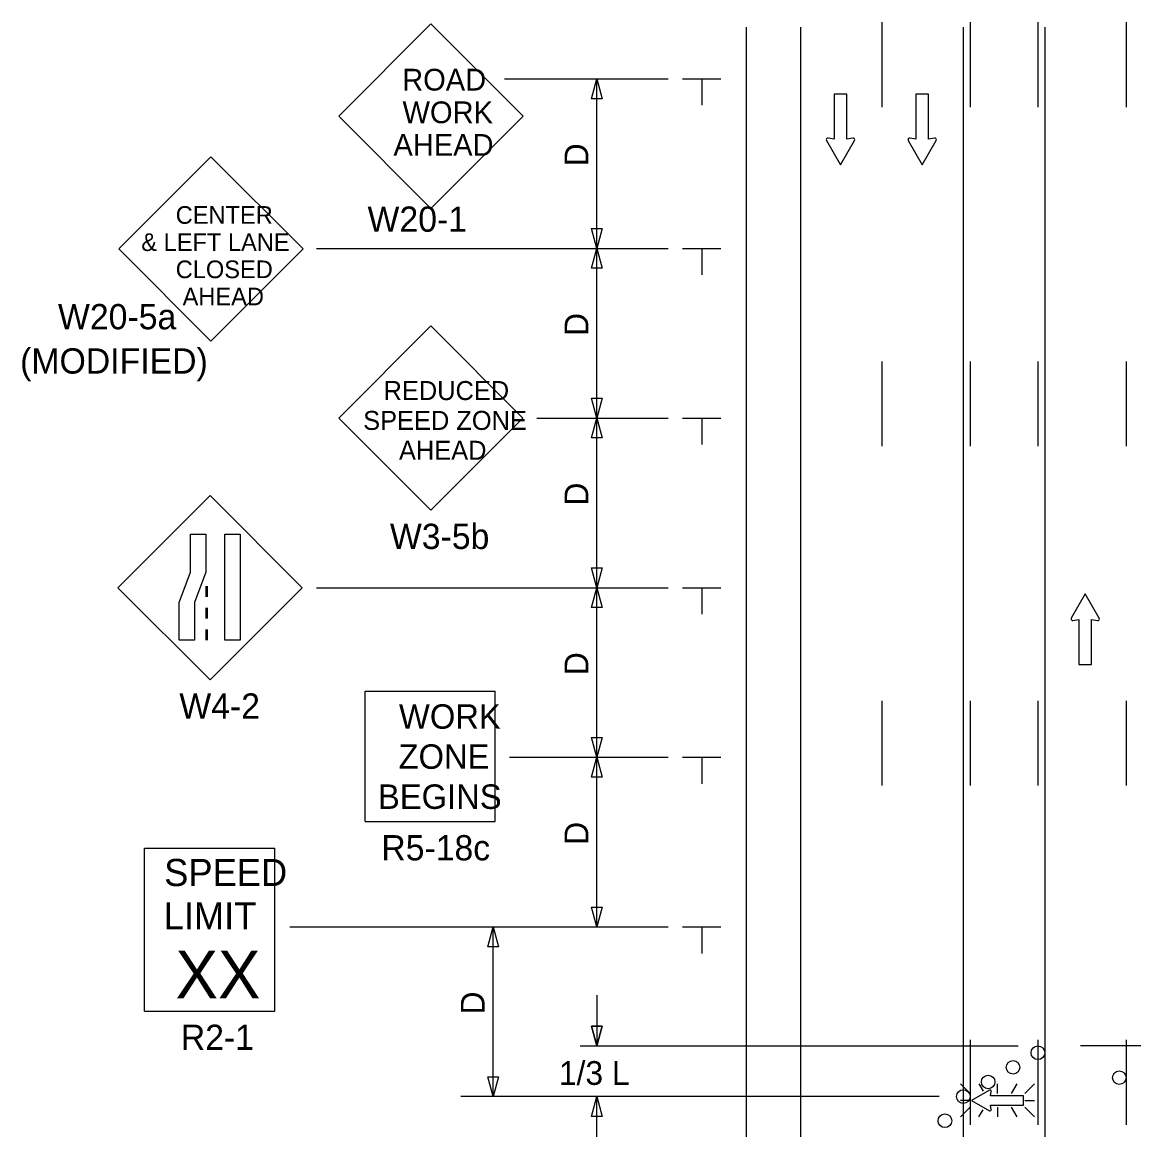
# Model space of a CAD drawing. Extents: x 16731 to 18475, y 5706 to 6928.
# Drawn here: x 16734 to 17061.7, y 6601.4 to 6927.9 of the extents above; entities that cross this region are included whole.
import ezdxf

# ---------------------------------------------------------------- set-up
doc = ezdxf.new("R2010")
doc.units = 0
for name, color, linetype in [('ALI_LEGAL_EX', 7, 'Continuous'), ('MT_SCRATCH_LEVEL_E', 7, 'Continuous'), ('PAVT_EDGE_EX', 7, 'Continuous'), ('TRAFFIC_SIGNS_PR', 7, 'Continuous'), ('TYPICAL_TEXT_DIMEN_PR', 7, 'Continuous')]:
    doc.layers.add(name, color=color, linetype=linetype)

msp = doc.modelspace()

# ---------------------------------------------------------------- linework, layer by layer
at = {"layer": 'ALI_LEGAL_EX'}
for points in [[(16987.43, 6927.88), (16987.43, 6902.88)], [(17013.43, 6927.88), (17013.43, 6902.88)], [(17033.43, 6927.88), (17033.43, 6902.88)], [(17059.43, 6927.88), (17059.43, 6902.88)], [(16987.43, 6827.88), (16987.43, 6802.88)], [(17013.43, 6827.88), (17013.43, 6802.88)], [(17033.43, 6827.88), (17033.43, 6802.88)], [(17059.43, 6827.88), (17059.43, 6802.88)], [(16987.43, 6727.88), (16987.43, 6702.88)], [(17013.43, 6727.88), (17013.43, 6702.88)], [(17033.43, 6727.88), (17033.43, 6702.88)], [(17059.43, 6727.88), (17059.43, 6702.88)], [(17013.43, 6627.88), (17013.43, 6602.88)], [(17033.43, 6627.88), (17033.43, 6602.88)], [(17059.43, 6627.88), (17059.43, 6602.88)]]:
    msp.add_lwpolyline(points, dxfattribs=at)
at = {"layer": 'MT_SCRATCH_LEVEL_E'}
for p, q in [((16977.1, 6906.67), (16973.36, 6906.67)), ((16973.36, 6906.67), (16973.36, 6893.41)), ((16977.1, 6906.67), (16973.36, 6906.67)), ((16973.36, 6906.67), (16973.36, 6893.41)), ((16977.1, 6893.41), (16977.1, 6906.67)), ((16977.1, 6893.41), (16977.1, 6906.67)), ((17001.17, 6906.67), (16997.43, 6906.67)), ((16997.43, 6906.67), (16997.43, 6893.41)), ((17001.17, 6906.67), (16997.43, 6906.67)), ((16997.43, 6906.67), (16997.43, 6893.41)), ((17001.17, 6893.41), (17001.17, 6906.67)), ((17001.17, 6893.41), (17001.17, 6906.67)), ((16971.1, 6893.05), (16975.25, 6885.81)), ((16971.1, 6893.05), (16975.25, 6885.81)), ((16973.36, 6893.41), (16971.58, 6893.73)), ((16973.36, 6893.41), (16971.58, 6893.73)), ((16975.25, 6885.81), (16979.36, 6893.05)), ((16975.25, 6885.81), (16979.36, 6893.05)), ((16978.88, 6893.73), (16977.1, 6893.41)), ((16978.88, 6893.73), (16977.1, 6893.41)), ((16995.18, 6893.05), (16999.32, 6885.81)), ((16995.18, 6893.05), (16999.32, 6885.81)), ((16997.43, 6893.41), (16995.65, 6893.73)), ((16997.43, 6893.41), (16995.65, 6893.73)), ((16999.32, 6885.81), (17003.43, 6893.05)), ((16999.32, 6885.81), (17003.43, 6893.05)), ((17002.95, 6893.73), (17001.17, 6893.41)), ((17002.95, 6893.73), (17001.17, 6893.41)), ((17047.37, 6759.44), (17043.26, 6752.2)), ((17047.37, 6759.44), (17043.26, 6752.2)), ((17051.52, 6752.2), (17047.37, 6759.44)), ((17051.52, 6752.2), (17047.37, 6759.44)), ((17043.74, 6751.51), (17045.52, 6751.83)), ((17043.74, 6751.51), (17045.52, 6751.83)), ((17045.52, 6751.83), (17045.52, 6738.57)), ((17045.52, 6751.83), (17045.52, 6738.57)), ((17049.26, 6738.57), (17049.26, 6751.83)), ((17049.26, 6751.83), (17051.04, 6751.51)), ((17049.26, 6738.57), (17049.26, 6751.83)), ((17049.26, 6751.83), (17051.04, 6751.51)), ((17045.52, 6738.57), (17049.26, 6738.57)), ((17045.52, 6738.57), (17049.26, 6738.57))]:
    msp.add_line(p, q, dxfattribs=at)
for centre, start, end in [((16971.51, 6893.27), 80.0362, 209.7731), ((16971.51, 6893.27), 80.0362, 209.7731), ((16978.96, 6893.27), 330.4248, 99.9638), ((16978.96, 6893.27), 330.4248, 99.9638), ((16995.59, 6893.27), 80.0362, 209.7731), ((16995.59, 6893.27), 80.0362, 209.7731), ((17003.03, 6893.27), 330.4248, 99.9638), ((17003.03, 6893.27), 330.4248, 99.9638), ((17043.67, 6751.97), 150.4248, 279.9638), ((17043.67, 6751.97), 150.4248, 279.9638), ((17051.11, 6751.97), 260.0362, 29.7731), ((17051.11, 6751.97), 260.0362, 29.7731)]:
    msp.add_arc(centre, 0.463, start, end, dxfattribs=at)
at = {"layer": 'PAVT_EDGE_EX'}
for p, q in [((16947.43, 6926.45), (16947.43, 6059.71)), ((16963.43, 6926.45), (16963.43, 6059.71)), ((17011.43, 6926.45), (17011.43, 6059.71)), ((17035.43, 6926.45), (17035.43, 6059.71))]:
    msp.add_line(p, q, dxfattribs=at)
at = {"layer": 'TRAFFIC_SIGNS_PR'}
for p, q in [((16854.47, 6927.38), (16827.28, 6900.19)), ((16881.66, 6900.19), (16854.47, 6927.38)), ((16827.28, 6900.19), (16854.47, 6873.01)), ((16854.47, 6873.01), (16881.66, 6900.19)), ((16789.62, 6888.24), (16762.43, 6861.05)), ((16816.81, 6861.05), (16789.62, 6888.24)), ((16762.43, 6861.05), (16789.62, 6833.86)), ((16789.62, 6833.86), (16816.81, 6861.05)), ((16854.45, 6838.36), (16827.3, 6811.2)), ((16881.6, 6811.2), (16854.45, 6838.36)), ((16827.3, 6811.2), (16854.45, 6784.05)), ((16854.45, 6784.05), (16881.6, 6811.2)), ((16789.36, 6788.36), (16762.2, 6761.2)), ((16816.51, 6761.2), (16789.36, 6788.36)), ((16762.2, 6761.2), (16789.36, 6734.05)), ((16788.11, 6761.69), (16788.11, 6758.49)), ((16788.51, 6761.69), (16788.51, 6758.49)), ((16789.36, 6734.05), (16816.51, 6761.2)), ((16788.11, 6755.29), (16788.11, 6752.09)), ((16788.51, 6755.29), (16788.51, 6752.09)), ((16788.11, 6748.89), (16788.11, 6745.69)), ((16788.51, 6748.89), (16788.51, 6745.69)), ((16835.05, 6692.26), (16835.05, 6730.66)), ((16835.05, 6730.66), (16873.45, 6730.66)), ((16873.45, 6692.26), (16873.45, 6730.66)), ((16835.05, 6692.26), (16873.45, 6692.26)), ((16770.07, 6684.4), (16808.47, 6684.4)), ((16770.07, 6636.4), (16770.07, 6684.4)), ((16808.47, 6636.4), (16808.47, 6684.4)), ((16770.07, 6636.4), (16808.47, 6636.4)), ((17010.62, 6614.93), (17013.44, 6612.11)), ((17017.34, 6612.75), (17016.08, 6614.93)), ((17021.52, 6612.11), (17021.52, 6614.93)), ((17025.65, 6612.11), (17027.28, 6614.93)), ((17029.6, 6612.11), (17032.43, 6614.93)), ((17013.44, 6610.08), (17010.62, 6610.08)), ((17029.6, 6610.08), (17032.43, 6610.08)), ((17010.62, 6605.23), (17013.44, 6608.05)), ((17016.05, 6605.23), (17017.26, 6607.32)), ((17021.52, 6608.05), (17021.52, 6605.23)), ((17027.31, 6605.23), (17025.68, 6608.05)), ((17029.6, 6608.05), (17032.43, 6605.23))]:
    msp.add_line(p, q, dxfattribs=at)
for points in [[(16788.11, 6776.94), (16788.11, 6765.76), (16784.77, 6756.88), (16784.77, 6745.69), (16780.27, 6745.69), (16780.27, 6756.88), (16783.62, 6765.76), (16783.62, 6776.94)], [(16798.25, 6776.94), (16798.25, 6745.69), (16793.75, 6745.69), (16793.75, 6776.94)]]:
    msp.add_lwpolyline(points, close=True, dxfattribs=at)
for points in [[(17019.19, 6613.1), (17013.88, 6610.08), (17019.19, 6607.04)], [(17019.69, 6607.4), (17019.46, 6608.69), (17029.19, 6608.69), (17029.19, 6611.44), (17019.46, 6611.44), (17019.69, 6612.74)]]:
    msp.add_lwpolyline(points, dxfattribs=at)
for centre in [(17033.42, 6624.12), (17026.09, 6619.82), (17018.76, 6615.51), (17057.41, 6616.77), (17011.43, 6611.2), (17006.01, 6604.07)]:
    msp.add_circle(centre, 2, dxfattribs=at)
for centre, start, end in [((17019.36, 6612.8), 350.7308, 118.8916), ((17019.36, 6607.34), 241.4833, 9.9593)]:
    msp.add_arc(centre, 0.341, start, end, dxfattribs=at)
at = {"layer": 'TYPICAL_TEXT_DIMEN_PR'}
for p, q in [((16876.2, 6911.2), (16924.43, 6911.2)), ((16901.86, 6905.34), (16903.43, 6911.2)), ((16903.43, 6861.2), (16903.43, 6911.2)), ((16903.43, 6911.2), (16905, 6905.34)), ((16928.68, 6911.2), (16939.93, 6911.2)), ((16934.31, 6911.2), (16934.31, 6903.42)), ((16903.43, 6905.34), (16901.86, 6905.34)), ((16905, 6905.34), (16903.43, 6905.34)), ((16903.43, 6861.2), (16901.86, 6867.07)), ((16901.86, 6867.07), (16903.43, 6867.07)), ((16903.43, 6867.07), (16905, 6867.07)), ((16905, 6867.07), (16903.43, 6861.2)), ((16820.78, 6861.2), (16924.43, 6861.2)), ((16898.43, 6861.2), (16924.43, 6861.2)), ((16901.86, 6855.34), (16903.43, 6861.2)), ((16903.43, 6811.2), (16903.43, 6861.2)), ((16903.43, 6861.2), (16905, 6855.34)), ((16928.68, 6861.2), (16939.93, 6861.2)), ((16934.31, 6861.2), (16934.31, 6853.42)), ((16903.43, 6855.34), (16901.86, 6855.34)), ((16905, 6855.34), (16903.43, 6855.34)), ((16903.43, 6811.2), (16901.86, 6817.07)), ((16901.86, 6817.07), (16903.43, 6817.07)), ((16903.43, 6817.07), (16905, 6817.07)), ((16905, 6817.07), (16903.43, 6811.2)), ((16885.75, 6811.2), (16924.43, 6811.2)), ((16898.43, 6811.2), (16924.43, 6811.2)), ((16901.86, 6805.34), (16903.43, 6811.2)), ((16903.43, 6811.2), (16905, 6805.34)), ((16903.43, 6761.2), (16903.43, 6811.2)), ((16928.68, 6811.2), (16939.93, 6811.2)), ((16934.31, 6811.2), (16934.31, 6803.42)), ((16903.43, 6805.34), (16901.86, 6805.34)), ((16905, 6805.34), (16903.43, 6805.34)), ((16903.43, 6761.2), (16901.86, 6767.07)), ((16901.86, 6767.07), (16903.43, 6767.07)), ((16903.43, 6767.07), (16905, 6767.07)), ((16905, 6767.07), (16903.43, 6761.2)), ((16820.78, 6761.2), (16924.43, 6761.2)), ((16901.86, 6755.34), (16903.43, 6761.2)), ((16903.43, 6761.2), (16905, 6755.34)), ((16903.43, 6711.2), (16903.43, 6761.2)), ((16928.68, 6761.2), (16939.93, 6761.2)), ((16934.31, 6761.2), (16934.31, 6753.42)), ((16903.43, 6755.34), (16901.86, 6755.34)), ((16905, 6755.34), (16903.43, 6755.34)), ((16903.43, 6711.2), (16901.86, 6717.07)), ((16901.86, 6717.07), (16903.43, 6717.07)), ((16903.43, 6717.07), (16905, 6717.07)), ((16905, 6717.07), (16903.43, 6711.2)), ((16877.68, 6711.2), (16924.43, 6711.2)), ((16901.86, 6705.34), (16903.43, 6711.2)), ((16903.43, 6711.2), (16905, 6705.34)), ((16903.43, 6661.2), (16903.43, 6711.2)), ((16928.68, 6711.2), (16939.93, 6711.2)), ((16934.31, 6711.2), (16934.31, 6703.42)), ((16903.43, 6705.34), (16901.86, 6705.34)), ((16905, 6705.34), (16903.43, 6705.34)), ((16903.43, 6661.2), (16901.86, 6667.07)), ((16901.86, 6667.07), (16903.43, 6667.07)), ((16903.43, 6667.07), (16905, 6667.07)), ((16905, 6667.07), (16903.43, 6661.2)), ((16812.89, 6661.2), (16924.43, 6661.2)), ((16871.29, 6655.34), (16872.86, 6661.2)), ((16872.86, 6611.2), (16872.86, 6661.2)), ((16872.86, 6661.2), (16874.43, 6655.34)), ((16928.68, 6661.2), (16939.93, 6661.2)), ((16934.31, 6661.2), (16934.31, 6653.42)), ((16872.86, 6655.34), (16871.29, 6655.34)), ((16874.43, 6655.34), (16872.86, 6655.34)), ((16903.43, 6641.05), (16903.43, 6626.12)), ((16903.43, 6626.12), (16901.86, 6631.99)), ((16901.86, 6631.99), (16903.43, 6631.99)), ((16903.43, 6631.99), (16901.86, 6631.99)), ((16901.86, 6631.99), (16903.43, 6626.12)), ((16903.43, 6631.99), (16905, 6631.99)), ((16905, 6631.99), (16903.43, 6626.12)), ((16903.43, 6626.12), (16905, 6631.99)), ((16905, 6631.99), (16903.43, 6631.99)), ((16898.43, 6626.12), (17027.57, 6626.12)), ((16898.43, 6626.12), (17000.85, 6626.12)), ((17148.43, 6626.12), (17046.02, 6626.12)), ((16872.86, 6611.2), (16871.29, 6617.07)), ((16871.29, 6617.07), (16872.86, 6617.07)), ((16872.86, 6617.07), (16874.43, 6617.07)), ((16874.43, 6617.07), (16872.86, 6611.2)), ((17004.35, 6611.2), (16863.34, 6611.2)), ((17004.35, 6611.2), (16872.86, 6611.2)), ((16901.86, 6605.34), (16903.43, 6611.2)), ((16903.43, 6580.67), (16903.43, 6611.2)), ((16903.43, 6611.2), (16905, 6605.34)), ((16903.43, 6605.34), (16901.86, 6605.34)), ((16905, 6605.34), (16903.43, 6605.34))]:
    msp.add_line(p, q, dxfattribs=at)

# ---------------------------------------------------------------- texts
at = {"layer": 'TRAFFIC_SIGNS_PR'}
for s, height, p in [('ROAD', 6.408, (16846, 6907.74)), ('WORK', 6.408, (16846.11, 6898.12)), ('AHEAD', 6.408, (16843.42, 6888.51)), ('CENTER', 5.206, (16779.24, 6868.46)), ('W20-1', 7.449, (16835.79, 6866.11)), ('& LEFT LANE', 5.2065, (16769.1, 6860.45)), ('CLOSED', 5.206, (16779.24, 6852.44)), ('AHEAD', 5.206, (16781.27, 6844.43)), ('W20-5a', 7.449, (16744.53, 6837.36)), ('(MODIFIED)', 7.449, (16733.37, 6824.31)), ('REDUCED', 5.6, (16840.51, 6816.51)), ('SPEED ZONE', 5.6, (16834.5, 6807.71)), ('AHEAD', 5.6, (16845.06, 6798.91)), ('W3-5b', 7.44, (16842.4, 6772.61)), ('W4-2', 7.44, (16780.31, 6722.61)), ('WORK', 7.217, (16845.05, 6719.62)), ('ZONE', 7.217, (16844.93, 6707.81)), ('BEGINS', 7.217, (16838.86, 6696)), ('R5-18c', 7.44, (16839.86, 6680.82)), ('SPEED', 8, (16775.84, 6673.26)), ('LIMIT', 8, (16775.68, 6660.46)), ('XX', 14.031, (16779.18, 6640.16)), ('R2-1', 7.44, (16780.75, 6624.96))]:
    msp.add_text(s, height=height, dxfattribs=at).set_placement(p)
at = {"layer": 'TYPICAL_TEXT_DIMEN_PR'}
for p in [(16900.88, 6885.42), (16900.88, 6835.42), (16900.88, 6785.42), (16900.88, 6735.42), (16900.88, 6685.42), (16870.3, 6635.42)]:
    msp.add_text('D', height=7, rotation=90, dxfattribs=at).set_placement(p)
msp.add_text('1/3 L', height=7, dxfattribs=at).set_placement((16892.22, 6614.65))

doc.saveas('drawing.dxf')
